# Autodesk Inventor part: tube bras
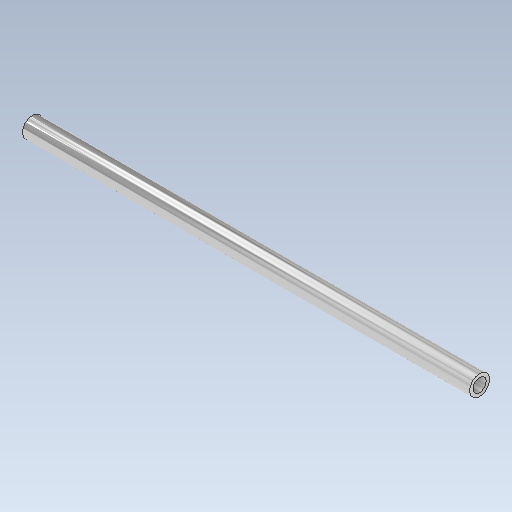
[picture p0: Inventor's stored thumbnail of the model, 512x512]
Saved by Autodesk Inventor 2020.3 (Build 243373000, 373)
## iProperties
Created: 2020-09
Part Number: tube bras
Material: Alliage de cuivre
Document SubType Name: Modeling
Designer: ficho
Density: 8.92 g/cm^3
Appearance: Chrome - Poli
Mass: 18.7754 g
Surface Area: 42.4115 cm^2
Volume: 2.10487 cm^3
Author: ficho
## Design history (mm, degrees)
sketch "Esquisse1"
  geometry: L1 (0, 3)-(134, 3); L2 (134, 3)-(134, 2); L3 (134, 2)-(0, 2); L4 (0, 2)-(0, 3); L5 (-26.8, 0)-(160.8, 0) reference; 1 further point
  constraints: 8 end point, 2 parallel, 1 horizontal, 1 perpendicular
  dimensions: "d0" = 134 distance of L2.end L3.end; "d1" = 1 distance of L1.end L2.end; "d2" = 2 distance from line of point (0, 0) L3; "d3" = 1 distance between parallel lines of L1 L3 (derived)
revolve "Révolution1" sketch "Esquisse1" stored, may be unused: angle "d4" = 90 deg
node "Solide1"
